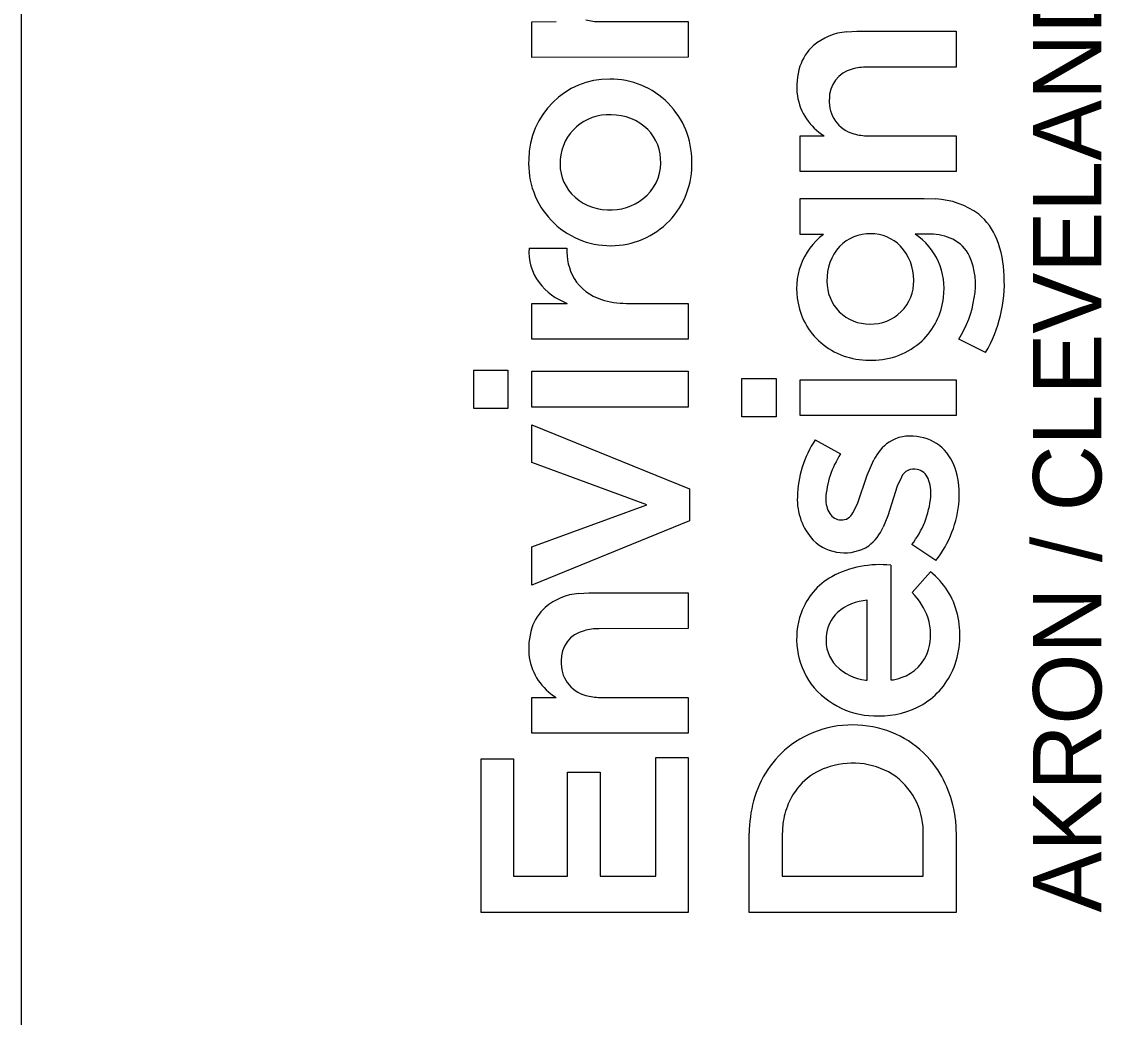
# Model space of a CAD drawing. Extents: x -0.4 to 34, y 0 to 22.
# Drawn here: x 32 to 32.901, y 2.551 to 3.381 of the extents above; entities that cross this region are included whole.
import ezdxf

# ---------------------------------------------------------------- set-up
doc = ezdxf.new("R2010")
doc.units = 0
doc.layers.add('SH_Border', color=7, linetype='Continuous')
doc.layers.add('SH_Data', color=7, linetype='Continuous')

msp = doc.modelspace()

# ---------------------------------------------------------------- linework, layer by layer
at = {"layer": 'SH_Border'}
msp.add_line((32, 0.5), (32, 21.5), dxfattribs=at)
at = {"layer": 'SH_Data'}
for p, q in [((32.42542, 3.38066), (32.44552, 3.38071)), ((32.42542, 3.35086), (32.42542, 3.38066)), ((32.48222, 3.38071), (32.55569, 3.38071)), ((32.55569, 3.38071), (32.55571, 3.35096)), ((32.68784, 3.3722), (32.69634, 3.37266)), ((32.69634, 3.37266), (32.77916, 3.37266)), ((32.77916, 3.37266), (32.77917, 3.34287)), ((32.55571, 3.35096), (32.42542, 3.35086)), ((32.77917, 3.34287), (32.70485, 3.3428)), ((32.64888, 3.2855), (32.66897, 3.28555)), ((32.64888, 3.25569), (32.64888, 3.2855)), ((32.70568, 3.28555), (32.77915, 3.28555)), ((32.77915, 3.28555), (32.77917, 3.25579)), ((32.77917, 3.25579), (32.64888, 3.25569)), ((32.6489, 3.20336), (32.64889, 3.23322)), ((32.64889, 3.23322), (32.75236, 3.23322)), ((32.75236, 3.23322), (32.76191, 3.23285)), ((32.66836, 3.20336), (32.6489, 3.20336)), ((32.75763, 3.20356), (32.74487, 3.20361)), ((32.42299, 3.19193), (32.45454, 3.19193)), ((32.42542, 3.14577), (32.45473, 3.14579)), ((32.42542, 3.11593), (32.42542, 3.14577)), ((32.50413, 3.14581), (32.55571, 3.14573)), ((32.55571, 3.14573), (32.55565, 3.11593)), ((32.55565, 3.11593), (32.42542, 3.11593)), ((32.8036, 3.10491), (32.7812, 3.11598)), ((32.37705, 3.05818), (32.37705, 3.09026)), ((32.37705, 3.09026), (32.40543, 3.09026)), ((32.40543, 3.09026), (32.40543, 3.05818)), ((32.42542, 3.05942), (32.42542, 3.08928)), ((32.42542, 3.08928), (32.55571, 3.08928)), ((32.55571, 3.08928), (32.55571, 3.05942)), ((32.60051, 3.05111), (32.60051, 3.08319)), ((32.60051, 3.08319), (32.62889, 3.08319)), ((32.62889, 3.08319), (32.62889, 3.05111)), ((32.64888, 3.05234), (32.64888, 3.0822)), ((32.64888, 3.0822), (32.77917, 3.0822)), ((32.77917, 3.0822), (32.77917, 3.05234)), ((32.40543, 3.05818), (32.37705, 3.05818)), ((32.55571, 3.05942), (32.42542, 3.05942)), ((32.62889, 3.05111), (32.60051, 3.05111)), ((32.77917, 3.05234), (32.64888, 3.05234)), ((32.42542, 3.01327), (32.42542, 3.0446)), ((32.42542, 3.0446), (32.5567, 2.9913)), ((32.66151, 3.03207), (32.68268, 3.02025)), ((32.52117, 2.97798), (32.42542, 3.01327)), ((32.70483, 3.00258), (32.71036, 3.01526)), ((32.69675, 2.97868), (32.70483, 3.00258)), ((32.73342, 3.00101), (32.72985, 2.9933)), ((32.5567, 2.9913), (32.5567, 2.96441)), ((32.72985, 2.9933), (32.72213, 2.96882)), ((32.42542, 2.94294), (32.52117, 2.97798)), ((32.69299, 2.97117), (32.69675, 2.97868)), ((32.5567, 2.96441), (32.42542, 2.91086)), ((32.72213, 2.96882), (32.71822, 2.95921)), ((32.42542, 2.91086), (32.42542, 2.94294)), ((32.76214, 2.93141), (32.74198, 2.94469)), ((32.72453, 2.92747), (32.72463, 2.83195)), ((32.74228, 2.90465), (32.75768, 2.922)), ((32.46439, 2.90397), (32.47289, 2.90443)), ((32.47289, 2.90443), (32.55571, 2.90443)), ((32.55571, 2.90443), (32.55571, 2.87465)), ((32.70489, 2.83182), (32.70489, 2.89834)), ((32.55571, 2.87465), (32.4814, 2.87457)), ((32.70361, 2.83165), (32.70489, 2.83182)), ((32.42542, 2.81728), (32.44552, 2.81733)), ((32.42542, 2.78747), (32.42542, 2.81728)), ((32.48222, 2.81733), (32.55569, 2.81733)), ((32.55569, 2.81733), (32.55571, 2.78756)), ((32.55571, 2.78756), (32.42542, 2.78747)), ((32.38298, 2.63791), (32.38298, 2.76598)), ((32.38298, 2.76598), (32.41012, 2.76598)), ((32.41012, 2.76598), (32.41012, 2.66827)), ((32.52857, 2.66827), (32.52857, 2.76722)), ((32.52857, 2.76722), (32.55571, 2.76722)), ((32.55571, 2.76722), (32.55571, 2.63791)), ((32.45503, 2.66827), (32.45503, 2.75488)), ((32.45503, 2.75488), (32.48218, 2.75488)), ((32.48218, 2.75488), (32.48218, 2.66827)), ((32.77847, 2.71497), (32.77917, 2.7021)), ((32.60643, 2.63799), (32.60644, 2.704)), ((32.63465, 2.71178), (32.63407, 2.7023)), ((32.63407, 2.7023), (32.63407, 2.66838)), ((32.75149, 2.66834), (32.75153, 2.70239)), ((32.77917, 2.7021), (32.77917, 2.638)), ((32.41012, 2.66827), (32.45503, 2.66827)), ((32.48218, 2.66827), (32.52857, 2.66827)), ((32.63407, 2.66838), (32.75149, 2.66834)), ((32.55571, 2.63791), (32.38298, 2.63791)), ((32.77917, 2.638), (32.60643, 2.63799))]:
    msp.add_line(p, q, dxfattribs=at)
for points in [[(32.42542, 3.35086), (32.42542, 3.38066), (32.44552, 3.38071)], [(32.48222, 3.38071), (32.55569, 3.38071), (32.55571, 3.35096), (32.42542, 3.35086)], [(32.68784, 3.3722), (32.69634, 3.37266), (32.77916, 3.37266), (32.77917, 3.34287), (32.70485, 3.3428)], [(32.64888, 3.25569), (32.64888, 3.2855), (32.66897, 3.28555)], [(32.70568, 3.28555), (32.77915, 3.28555), (32.77917, 3.25579), (32.64888, 3.25569)], [(32.66836, 3.20336), (32.6489, 3.20336), (32.64889, 3.23322), (32.75236, 3.23322), (32.76191, 3.23285)], [(32.75763, 3.20356), (32.74487, 3.20361)], [(32.42299, 3.19193), (32.45454, 3.19193)], [(32.50413, 3.14581), (32.55571, 3.14573), (32.55565, 3.11593), (32.42542, 3.11593)], [(32.42542, 3.11593), (32.42542, 3.14577), (32.45473, 3.14579)], [(32.8036, 3.10491), (32.7812, 3.11598)], [(32.66151, 3.03207), (32.68268, 3.02025)], [(32.69299, 2.97117), (32.69675, 2.97868), (32.70483, 3.00258), (32.71036, 3.01526)], [(32.73342, 3.00101), (32.72985, 2.9933), (32.72213, 2.96882), (32.71822, 2.95921)], [(32.76214, 2.93141), (32.74198, 2.94469)], [(32.72453, 2.92747), (32.72463, 2.83195)], [(32.74228, 2.90465), (32.75768, 2.922)], [(32.46439, 2.90397), (32.47289, 2.90443), (32.55571, 2.90443), (32.55571, 2.87465), (32.4814, 2.87457)], [(32.70361, 2.83165), (32.70489, 2.83182), (32.70489, 2.89834)], [(32.42542, 2.78747), (32.42542, 2.81728), (32.44552, 2.81733)], [(32.48222, 2.81733), (32.55569, 2.81733), (32.55571, 2.78756), (32.42542, 2.78747)], [(32.77847, 2.71497), (32.77917, 2.7021), (32.77917, 2.638), (32.60643, 2.63799)], [(32.60643, 2.63799), (32.60644, 2.704)], [(32.63465, 2.71178), (32.63407, 2.7023), (32.63407, 2.66838), (32.75149, 2.66834), (32.75153, 2.70239)]]:
    msp.add_lwpolyline(points, dxfattribs=at)
for points in [[(32.37705, 3.05818), (32.37705, 3.09026), (32.40543, 3.09026), (32.40543, 3.05818)], [(32.42542, 3.05942), (32.42542, 3.08928), (32.55571, 3.08928), (32.55571, 3.05942)], [(32.60051, 3.05111), (32.60051, 3.08319), (32.62889, 3.08319), (32.62889, 3.05111)], [(32.64888, 3.05234), (32.64888, 3.0822), (32.77917, 3.0822), (32.77917, 3.05234)], [(32.42542, 2.91086), (32.42542, 2.94294), (32.52117, 2.97798), (32.42542, 3.01327), (32.42542, 3.0446), (32.5567, 2.9913), (32.5567, 2.96441)], [(32.38298, 2.63791), (32.38298, 2.76598), (32.41012, 2.76598), (32.41012, 2.66827), (32.45503, 2.66827), (32.45503, 2.75488), (32.48218, 2.75488), (32.48218, 2.66827), (32.52857, 2.66827), (32.52857, 2.76722), (32.55571, 2.76722), (32.55571, 2.63791)]]:
    msp.add_lwpolyline(points, close=True, dxfattribs=at)
for centre, radius, start, end in [((32.48183, 3.42286), 0.04215, 254.08913, 270.52838), ((32.48183, 3.42286), 0.04215, 254.08913, 270.52838), ((32.69216, 3.32251), 0.04988, 94.97056, 130.22484), ((32.69216, 3.32251), 0.04988, 94.97056, 130.22484), ((32.68694, 3.33085), 0.04016, 132.22383, 161.68229), ((32.68694, 3.33085), 0.04016, 132.22383, 161.68229), ((32.70217, 3.32642), 0.05602, 162.27398, 187.79173), ((32.70217, 3.32642), 0.05602, 162.27398, 187.79173), ((32.70453, 3.29679), 0.04601, 89.60515, 105.33026), ((32.70453, 3.29679), 0.04601, 89.60515, 105.33026), ((32.69828, 3.31689), 0.02498, 103.68683, 182.21395), ((32.69828, 3.31689), 0.02498, 103.68683, 182.21395), ((32.49014, 3.26543), 0.0674, 89.84756, 179.64047), ((32.49014, 3.26543), 0.0674, 89.84756, 179.64047), ((32.49057, 3.26474), 0.0681, 359.54009, 90.21138), ((32.49057, 3.26474), 0.0681, 359.54009, 90.21138), ((32.69372, 3.32624), 0.04763, 188.96462, 238.69865), ((32.69372, 3.32624), 0.04763, 188.96462, 238.69865), ((32.7008, 3.31381), 0.02757, 175.58441, 255.13816), ((32.7008, 3.31381), 0.02757, 175.58441, 255.13816), ((32.48923, 3.26263), 0.0404, 87.04809, 175.57259), ((32.48923, 3.26263), 0.0404, 87.04809, 175.57259), ((32.49204, 3.25999), 0.04299, 45.84264, 90.98008), ((32.49204, 3.25999), 0.04299, 45.84264, 90.98008), ((32.49458, 3.26421), 0.03821, 357.88569, 44.15902), ((32.49458, 3.26421), 0.03821, 357.88569, 44.15902), ((32.70529, 3.32769), 0.04215, 254.08913, 270.52838), ((32.70529, 3.32769), 0.04215, 254.08913, 270.52838), ((32.49083, 3.26209), 0.06819, 176.8344, 270.40384), ((32.49083, 3.26209), 0.06819, 176.8344, 270.40384), ((32.48729, 3.2625), 0.03848, 175.15378, 221.14706), ((32.48729, 3.2625), 0.03848, 175.15378, 221.14706), ((32.49123, 3.26139), 0.06749, 270.06243, 2.37759), ((32.49123, 3.26139), 0.06749, 270.06243, 2.37759), ((32.49446, 3.26318), 0.0383, 308.28936, 359.43468), ((32.49446, 3.26318), 0.0383, 308.28936, 359.43468), ((32.48919, 3.26607), 0.04228, 223.09994, 268.80895), ((32.48919, 3.26607), 0.04228, 223.09994, 268.80895), ((32.49096, 3.2679), 0.04418, 266.56515, 308.06078), ((32.49096, 3.2679), 0.04418, 266.56515, 308.06078), ((32.75907, 3.16789), 0.06503, 53.40344, 87.49062), ((32.75907, 3.16789), 0.06503, 53.40344, 87.49062), ((32.76517, 3.18039), 0.05141, 21.60748, 50.5577), ((32.76517, 3.18039), 0.05141, 21.60748, 50.5577), ((32.70292, 3.15813), 0.05692, 127.37482, 192.22468), ((32.70292, 3.15813), 0.05692, 127.37482, 192.22468), ((32.70693, 3.16927), 0.0346, 88.47302, 136.42562), ((32.70693, 3.16927), 0.0346, 88.47302, 136.42562), ((32.70814, 3.16963), 0.03424, 44.27195, 90.47623), ((32.70814, 3.16963), 0.03424, 44.27195, 90.47623), ((32.71421, 3.15829), 0.05472, 352.1125, 55.92295), ((32.71421, 3.15829), 0.05472, 352.1125, 55.92295), ((32.75666, 3.15725), 0.04633, 65.01687, 88.8011), ((32.75666, 3.15725), 0.04633, 65.01687, 88.8011), ((32.7626, 3.17155), 0.03085, 26.26808, 63.80301), ((32.7626, 3.17155), 0.03085, 26.26808, 63.80301), ((32.73069, 3.16714), 0.08835, 1.15143, 21.3627), ((32.73069, 3.16714), 0.08835, 1.15143, 21.3627), ((32.46616, 3.18882), 0.04329, 175.87313, 216.34747), ((32.46616, 3.18882), 0.04329, 175.87313, 216.34747), ((32.50087, 3.18948), 0.04639, 176.9688, 209.60636), ((32.50087, 3.18948), 0.04639, 176.9688, 209.60636), ((32.71141, 3.16602), 0.0401, 137.46739, 182.33237), ((32.71141, 3.16602), 0.0401, 137.46739, 182.33237), ((32.70368, 3.166), 0.03996, 358.57141, 43.53765), ((32.70368, 3.166), 0.03996, 358.57141, 43.53765), ((32.73565, 3.16154), 0.05953, 349.30734, 23.43071), ((32.73565, 3.16154), 0.05953, 349.30734, 23.43071), ((32.47466, 3.19716), 0.05511, 218.09809, 248.7907), ((32.47466, 3.19716), 0.05511, 218.09809, 248.7907), ((32.49514, 3.18814), 0.04079, 211.94466, 253.2028), ((32.49514, 3.18814), 0.04079, 211.94466, 253.2028), ((32.70645, 3.1637), 0.03511, 178.88208, 271.08374), ((32.70645, 3.1637), 0.03511, 178.88208, 271.08374), ((32.70818, 3.16404), 0.03546, 268.27882, 1.55016), ((32.70818, 3.16404), 0.03546, 268.27882, 1.55016), ((32.70538, 3.16244), 0.11383, 329.6388, 3.25998), ((32.70538, 3.16244), 0.11383, 329.6388, 3.25998), ((32.50465, 3.2165), 0.07069, 252.46555, 269.57296), ((32.50465, 3.2165), 0.07069, 252.46555, 269.57296), ((32.70463, 3.15696), 0.05837, 190.75182, 231.28919), ((32.70463, 3.15696), 0.05837, 190.75182, 231.28919), ((32.70988, 3.15708), 0.05887, 313.74196, 353.8554), ((32.70988, 3.15708), 0.05887, 313.74196, 353.8554), ((32.70738, 3.16334), 0.08771, 327.31495, 351.57478), ((32.70738, 3.16334), 0.08771, 327.31495, 351.57478), ((32.70632, 3.16112), 0.06269, 232.46061, 272.59022), ((32.70632, 3.16112), 0.06269, 232.46061, 272.59022), ((32.70954, 3.15901), 0.06051, 269.6361, 312.70877), ((32.70954, 3.15901), 0.06051, 269.6361, 312.70877), ((32.73636, 2.98258), 0.08973, 146.53104, 178.7571), ((32.73636, 2.98258), 0.08973, 146.53104, 178.7571), ((32.74661, 2.99713), 0.04053, 125.51182, 153.41595), ((32.74661, 2.99713), 0.04053, 125.51182, 153.41595), ((32.7406, 3.0026), 0.03263, 80.17192, 122.51969), ((32.7406, 3.0026), 0.03263, 80.17192, 122.51969), ((32.74278, 2.99824), 0.03667, 47.79344, 84.68918), ((32.74278, 2.99824), 0.03667, 47.79344, 84.68918), ((32.74519, 2.9789), 0.07495, 146.51121, 176.91007), ((32.74519, 2.9789), 0.07495, 146.51121, 176.91007), ((32.73788, 2.9946), 0.04267, 14.9966, 46.20632), ((32.73788, 2.9946), 0.04267, 14.9966, 46.20632), ((32.74384, 2.99631), 0.01143, 76.66094, 155.7053), ((32.74384, 2.99631), 0.01143, 76.66094, 155.7053), ((32.74397, 2.99511), 0.01256, 21.5098, 78.52618), ((32.74397, 2.99511), 0.01256, 21.5098, 78.52618), ((32.71044, 2.98674), 0.07121, 355.83062, 15.39138), ((32.71044, 2.98674), 0.07121, 355.83062, 15.39138), ((32.72592, 2.98766), 0.03209, 354.57264, 22.06805), ((32.72592, 2.98766), 0.03209, 354.57264, 22.06805), ((32.69666, 2.98238), 0.05005, 177.53659, 222.79318), ((32.69666, 2.98238), 0.05005, 177.53659, 222.79318), ((32.6931, 2.98233), 0.02276, 178.47474, 211.08679), ((32.6931, 2.98233), 0.02276, 178.47474, 211.08679), ((32.68248, 2.99149), 0.0757, 321.81101, 354.79685), ((32.68248, 2.99149), 0.0757, 321.81101, 354.79685), ((32.68952, 2.9882), 0.09219, 321.9777, 355.87384), ((32.68952, 2.9882), 0.09219, 321.9777, 355.87384), ((32.68331, 2.9767), 0.01148, 212.23676, 268.37769), ((32.68331, 2.9767), 0.01148, 212.23676, 268.37769), ((32.68342, 2.97589), 0.01067, 267.71603, 333.73375), ((32.68342, 2.97589), 0.01067, 267.71603, 333.73375), ((32.68098, 2.9758), 0.04077, 308.08772, 335.98736), ((32.68098, 2.9758), 0.04077, 308.08772, 335.98736), ((32.68599, 2.97535), 0.0375, 225.98539, 302.47965), ((32.68599, 2.97535), 0.0375, 225.98539, 302.47965), ((32.7152, 2.84414), 0.08384, 83.61499, 118.28755), ((32.7152, 2.84414), 0.08384, 83.61499, 118.28755), ((32.71744, 2.87167), 0.06443, 13.53365, 51.36148), ((32.71744, 2.87167), 0.06443, 13.53365, 51.36148), ((32.70239, 2.86906), 0.05583, 118.83082, 160.62438), ((32.70239, 2.86906), 0.05583, 118.83082, 160.62438), ((32.46871, 2.85428), 0.04988, 94.96958, 130.22249), ((32.46871, 2.85428), 0.04988, 94.96958, 130.22249), ((32.70378, 2.86556), 0.05486, 19.03571, 45.44059), ((32.70378, 2.86556), 0.05486, 19.03571, 45.44059), ((32.46348, 2.86263), 0.04015, 132.22192, 161.68183), ((32.46348, 2.86263), 0.04015, 132.22192, 161.68183), ((32.70785, 2.85609), 0.04235, 94.00805, 130.88169), ((32.70785, 2.85609), 0.04235, 94.00805, 130.88169), ((32.71041, 2.86612), 0.06437, 160.52012, 215.78311), ((32.71041, 2.86612), 0.06437, 160.52012, 215.78311), ((32.70048, 2.86628), 0.02985, 132.98507, 177.179), ((32.70048, 2.86628), 0.02985, 132.98507, 177.179), ((32.71069, 2.8697), 0.047, 344.60586, 17.007), ((32.71069, 2.8697), 0.047, 344.60586, 17.007), ((32.70635, 2.86921), 0.07579, 339.3542, 13.37853), ((32.70635, 2.86921), 0.07579, 339.3542, 13.37853), ((32.47872, 2.85819), 0.05601, 162.27355, 187.79185), ((32.47872, 2.85819), 0.05601, 162.27355, 187.79185), ((32.48108, 2.82856), 0.04601, 89.60494, 105.3284), ((32.48108, 2.82856), 0.04601, 89.60494, 105.3284), ((32.47482, 2.84867), 0.02498, 103.68646, 182.21874), ((32.47482, 2.84867), 0.02498, 103.68646, 182.21874), ((32.7017, 2.86503), 0.03115, 175.00126, 223.28301), ((32.7017, 2.86503), 0.03115, 175.00126, 223.28301), ((32.7224, 2.86715), 0.03504, 288.00773, 343.55078), ((32.7224, 2.86715), 0.03504, 288.00773, 343.55078), ((32.47026, 2.85802), 0.04762, 188.96199, 238.70369), ((32.47026, 2.85802), 0.04762, 188.96199, 238.70369), ((32.47735, 2.84558), 0.02756, 175.58538, 255.14386), ((32.47735, 2.84558), 0.02756, 175.58538, 255.14386), ((32.70891, 2.87363), 0.04231, 225.06188, 262.79738), ((32.70891, 2.87363), 0.04231, 225.06188, 262.79738), ((32.71894, 2.8652), 0.0626, 300.94269, 338.73225), ((32.71894, 2.8652), 0.0626, 300.94269, 338.73225), ((32.72474, 2.85216), 0.02021, 269.7003, 294.8711), ((32.72474, 2.85216), 0.02021, 269.7003, 294.8711), ((32.71253, 2.87054), 0.06872, 217.74516, 271.65431), ((32.71253, 2.87054), 0.06872, 217.74516, 271.65431), ((32.48183, 2.85948), 0.04215, 254.09162, 270.52835), ((32.48183, 2.85948), 0.04215, 254.09162, 270.52835), ((32.71549, 2.87241), 0.07056, 269.20477, 300.33412), ((32.71549, 2.87241), 0.07056, 269.20477, 300.33412), ((32.69229, 2.70792), 0.08641, 81.19402, 125.99844), ((32.69229, 2.70792), 0.08641, 81.19402, 125.99844), ((32.69458, 2.71132), 0.08272, 37.85208, 82.40204), ((32.69458, 2.71132), 0.08272, 37.85208, 82.40204), ((32.69387, 2.70893), 0.08654, 127.23621, 165.14796), ((32.69387, 2.70893), 0.08654, 127.23621, 165.14796), ((32.68893, 2.70782), 0.05398, 106.18808, 157.38609), ((32.68893, 2.70782), 0.05398, 106.18808, 157.38609), ((32.69279, 2.69862), 0.06389, 55.67272, 107.20935), ((32.69279, 2.69862), 0.06389, 55.67272, 107.20935), ((32.68586, 2.70567), 0.09308, 5.73329, 37.30396), ((32.68586, 2.70567), 0.09308, 5.73329, 37.30396), ((32.69291, 2.70499), 0.05867, 357.46616, 52.26647), ((32.69291, 2.70499), 0.05867, 357.46616, 52.26647), ((32.71426, 2.70281), 0.10783, 164.7861, 179.37039), ((32.71426, 2.70281), 0.10783, 164.7861, 179.37039), ((32.69829, 2.70389), 0.06412, 157.35705, 172.92755), ((32.69829, 2.70389), 0.06412, 157.35705, 172.92755)]:
    msp.add_arc(centre, radius, start, end, dxfattribs=at)

# ---------------------------------------------------------------- texts
msp.add_text('AKRON / CLEVELAND / COLUMBUS', height=0.056969, rotation=90, dxfattribs=at).set_placement((32.90012, 2.638))

doc.saveas('drawing.dxf')
